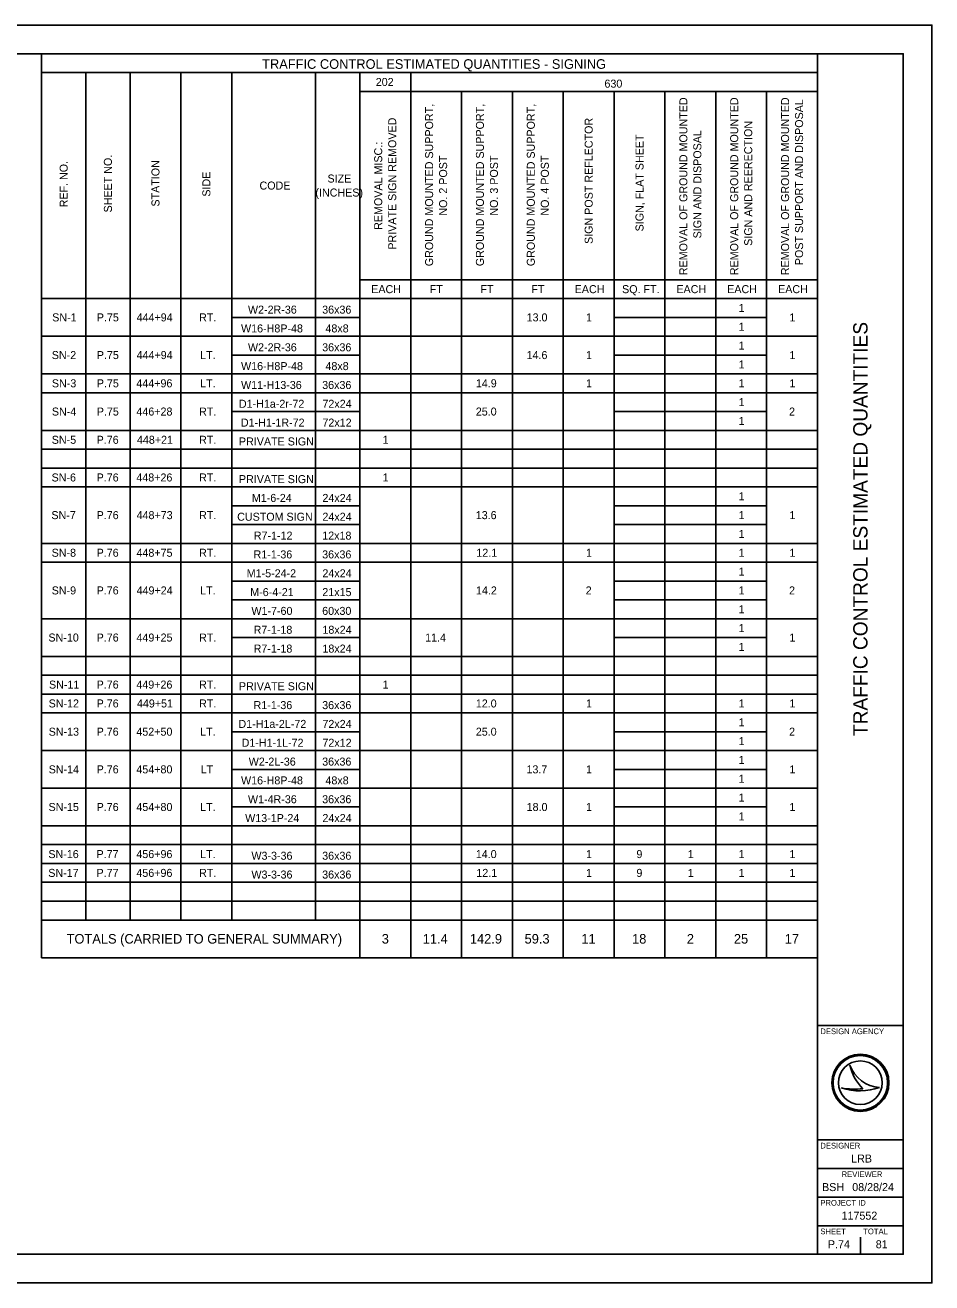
# Model space of a CAD drawing. Extents: x 0 to 34, y 0 to 22.
# Drawn here: x 18.14 to 34, y 0 to 22 of the extents above; entities that cross this region are included whole.
import ezdxf

# ---------------------------------------------------------------- set-up
doc = ezdxf.new("R2010")
doc.units = 0
for name, color, linetype in [('SH_Border', 7, 'Continuous'), ('SH_Cut_Line', 7, 'Continuous'), ('SH_Data', 7, 'Continuous'), ('SH_Text', 7, 'Continuous')]:
    doc.layers.add(name, color=color, linetype=linetype)

msp = doc.modelspace()

# ---------------------------------------------------------------- linework, layer by layer
at = {"layer": 'SH_Border'}
for p, q in [((32, 0.5), (32, 21.5)), ((32, 4.5), (33.5, 4.5)), ((32, 2.5), (33.5, 2.5)), ((32, 2), (33.5, 2)), ((32, 1.5), (33.5, 1.5)), ((32, 1), (33.5, 1))]:
    msp.add_line(p, q, dxfattribs=at)
msp.add_lwpolyline([(1.5, 21.5), (33.5, 21.5), (33.5, 0.5), (1.5, 0.5)], close=True, dxfattribs=at)
at = {"layer": 'SH_Cut_Line'}
msp.add_lwpolyline([(0, 0), (34, 0), (34, 22), (0, 22)], close=True, dxfattribs=at)
at = {"layer": 'SH_Data'}
for p, q in [((32.567, 3.81), (32.567, 3.81)), ((32.417, 3.41), (32.417, 3.41)), ((32.75, 3.5), (32.75, 3.5)), ((33.087, 3.419), (33.087, 3.419)), ((32.375, 0.675), (32.375, 0.675)), ((32.75, 0.5), (32.75, 0.8))]:
    msp.add_line(p, q, dxfattribs=at)
for radius in [0.5, 0.477, 0.477, 0.382]:
    msp.add_circle((32.75, 3.5), radius, dxfattribs=at)
for centre, radius, start, end in [((33.116, 3.998), 0.58, 198.9257, 198.9319), ((33.347, 3.97), 0.796, 191.6379, 191.6421), ((33.116, 3.998), 0.58, 198.9319, 267.1657), ((33.347, 3.97), 0.796, 191.6421, 226.0947), ((32.739, 4.37), 1.013, 251.4576, 290.0832), ((32.648, 4.654), 1.266, 259.4964, 259.4995), ((32.739, 4.37), 1.013, 251.4527, 251.4576), ((32.648, 4.654), 1.266, 259.4995, 276.6672)]:
    msp.add_arc(centre, radius, start, end, dxfattribs=at)
at = {"layer": 'SH_Text'}
for p, q in [((18.428, 21.5), (32, 21.5)), ((18.428, 21.5), (18.428, 5.688)), ((32, 21.5), (32, 5.688)), ((18.428, 21.171), (32, 21.171)), ((19.202, 21.171), (19.202, 6.347)), ((19.976, 21.171), (19.976, 6.347)), ((20.866, 21.171), (20.866, 6.347)), ((21.755, 21.171), (21.755, 6.347)), ((23.221, 21.171), (23.221, 6.347)), ((23.995, 21.171), (23.995, 5.688)), ((24.885, 21.171), (24.885, 5.688)), ((23.995, 20.841), (32, 20.841)), ((25.774, 20.841), (25.774, 5.688)), ((26.664, 20.841), (26.664, 5.688)), ((27.553, 20.841), (27.553, 5.688)), ((28.442, 20.841), (28.442, 5.688)), ((29.332, 20.841), (29.332, 5.688)), ((30.221, 20.841), (30.221, 5.688)), ((31.111, 20.841), (31.111, 6.347)), ((23.995, 17.547), (32, 17.547)), ((18.428, 17.218), (32, 17.218)), ((21.755, 16.888), (23.995, 16.888)), ((28.442, 16.888), (31.111, 16.888)), ((18.428, 16.559), (32, 16.559)), ((21.755, 16.229), (23.995, 16.229)), ((28.442, 16.229), (31.111, 16.229)), ((18.428, 15.9), (32, 15.9)), ((18.428, 15.571), (32, 15.571)), ((21.755, 15.241), (23.995, 15.241)), ((28.442, 15.241), (31.111, 15.241)), ((18.428, 14.912), (32, 14.912)), ((18.428, 14.582), (32, 14.582)), ((18.428, 14.253), (32, 14.253)), ((18.428, 13.924), (32, 13.924)), ((21.755, 13.594), (23.995, 13.594)), ((28.442, 13.594), (31.111, 13.594)), ((21.755, 13.265), (23.995, 13.265)), ((28.442, 13.265), (31.111, 13.265)), ((18.428, 12.935), (32, 12.935)), ((18.428, 12.606), (32, 12.606)), ((21.755, 12.276), (23.995, 12.276)), ((28.442, 12.276), (31.111, 12.276)), ((21.755, 11.947), (23.995, 11.947)), ((28.442, 11.947), (31.111, 11.947)), ((18.428, 11.618), (32, 11.618)), ((21.755, 11.288), (23.995, 11.288)), ((28.442, 11.288), (31.111, 11.288)), ((18.428, 10.959), (32, 10.959)), ((18.428, 10.629), (32, 10.629)), ((18.428, 10.3), (32, 10.3)), ((18.428, 9.971), (32, 9.971)), ((21.755, 9.641), (23.995, 9.641)), ((28.442, 9.641), (31.111, 9.641)), ((18.428, 9.312), (32, 9.312)), ((21.755, 8.982), (23.995, 8.982)), ((28.442, 8.982), (31.111, 8.982)), ((18.428, 8.653), (32, 8.653)), ((21.755, 8.324), (23.995, 8.324)), ((28.442, 8.324), (31.111, 8.324)), ((18.428, 7.994), (32, 7.994)), ((18.428, 7.665), (32, 7.665)), ((18.428, 7.335), (32, 7.335)), ((18.428, 7.006), (32, 7.006)), ((18.428, 6.676), (32, 6.676)), ((18.428, 6.347), (32, 6.347)), ((31.111, 6.347), (31.111, 5.688)), ((18.428, 5.688), (32, 5.688))]:
    msp.add_line(p, q, dxfattribs=at)

# ---------------------------------------------------------------- texts
at = {"layer": 'SH_Data'}
msp.add_text('TRAFFIC CONTROL ESTIMATED QUANTITIES', height=0.25, rotation=90, dxfattribs=at).set_placement((32.875, 9.565))
for s, height, p in [('DESIGN AGENCY', 0.1, (32.05, 4.35)), ('DESIGNER', 0.1, (32.05, 2.35)), ('LRB', 0.14, (32.589, 2.105)), ('REVIEWER', 0.1, (32.422, 1.85)), ('BSH', 0.14, (32.08, 1.605)), ('08/28/24', 0.14, (32.608, 1.605)), ('PROJECT ID', 0.1, (32.05, 1.35)), ('117552', 0.14, (32.421, 1.105)), ('SHEET', 0.1, (32.05, 0.85)), ('TOTAL', 0.1, (32.8, 0.85)), ('P.74', 0.14, (32.182, 0.605)), ('81', 0.14, (33.019, 0.605))]:
    msp.add_text(s, height=height, dxfattribs=at).set_placement(p)
at = {"layer": 'SH_Text'}
for s, height, p in [('TRAFFIC CONTROL ESTIMATED QUANTITIES - SIGNING', 0.168, (22.286, 21.236)), ('202', 0.14, (24.274, 20.936)), ('630', 0.14, (28.274, 20.907)), ('SIZE ', 0.14, (23.43, 19.247)), ('CODE', 0.14, (22.241, 19.124)), ('(INCHES)', 0.14, (23.219, 19.002)), ('EACH', 0.14, (24.195, 17.312)), ('FT', 0.14, (25.217, 17.312)), ('FT', 0.14, (26.106, 17.312)), ('FT', 0.14, (26.995, 17.312)), ('EACH', 0.14, (27.753, 17.312)), ('SQ. FT.', 0.14, (28.582, 17.312)), ('EACH', 0.14, (29.532, 17.312)), ('EACH', 0.14, (30.421, 17.312)), ('EACH', 0.14, (31.311, 17.312)), ('SN-1', 0.14, (18.615, 16.818)), ('P.75', 0.14, (19.395, 16.818)), ('444+94', 0.14, (20.091, 16.818)), ('RT.', 0.14, (21.184, 16.818)), ('W2-2R-36', 0.14, (22.039, 16.954)), ('36x36', 0.14, (23.337, 16.954)), ('13.0', 0.14, (26.913, 16.818)), ('1', 0.14, (27.952, 16.818)), ('1', 0.14, (30.62, 16.983)), ('1', 0.14, (31.509, 16.818)), ('W16-H8P-48', 0.14, (21.918, 16.625)), ('48x8', 0.14, (23.394, 16.625)), ('1', 0.14, (30.62, 16.654)), ('SN-2', 0.14, (18.608, 16.159)), ('P.75', 0.14, (19.395, 16.159)), ('444+94', 0.14, (20.091, 16.159)), ('LT.', 0.14, (21.203, 16.159)), ('W2-2R-36', 0.14, (22.039, 16.295)), ('36x36', 0.14, (23.337, 16.295)), ('14.6', 0.14, (26.912, 16.159)), ('1', 0.14, (27.952, 16.159)), ('1', 0.14, (30.62, 16.324)), ('1', 0.14, (31.509, 16.159)), ('W16-H8P-48', 0.14, (21.918, 15.966)), ('48x8', 0.14, (23.394, 15.966)), ('1', 0.14, (30.62, 15.995)), ('SN-3', 0.14, (18.609, 15.665)), ('P.75', 0.14, (19.395, 15.665)), ('444+96', 0.14, (20.087, 15.665)), ('LT.', 0.14, (21.203, 15.665)), ('W11-H13-36', 0.14, (21.918, 15.636)), ('36x36', 0.14, (23.337, 15.636)), ('14.9', 0.14, (26.025, 15.665)), ('1', 0.14, (27.952, 15.665)), ('1', 0.14, (30.62, 15.665)), ('1', 0.14, (31.509, 15.665)), ('D1-H1a-2r-72', 0.14, (21.88, 15.307)), ('72x24', 0.14, (23.341, 15.307)), ('1', 0.14, (30.62, 15.336)), ('SN-4', 0.14, (18.609, 15.171)), ('P.75', 0.14, (19.395, 15.171)), ('446+28', 0.14, (20.088, 15.171)), ('RT.', 0.14, (21.184, 15.171)), ('25.0', 0.14, (26.024, 15.171)), ('2', 0.14, (31.503, 15.171)), ('D1-H1-1R-72', 0.14, (21.915, 14.978)), ('72x12', 0.14, (23.341, 14.978)), ('1', 0.14, (30.62, 15.006)), ('SN-5', 0.14, (18.607, 14.677)), ('P.76', 0.14, (19.392, 14.677)), ('448+21', 0.14, (20.097, 14.677)), ('RT.', 0.14, (21.184, 14.677)), ('PRIVATE SIGN', 0.14, (21.881, 14.648)), ('1', 0.14, (24.394, 14.677)), ('SN-6', 0.14, (18.604, 14.018)), ('P.76', 0.14, (19.392, 14.018)), ('448+26', 0.14, (20.087, 14.018)), ('RT.', 0.14, (21.184, 14.018)), ('PRIVATE SIGN', 0.14, (21.881, 13.989)), ('1', 0.14, (24.394, 14.018)), ('M1-6-24', 0.14, (22.107, 13.66)), ('24x24', 0.14, (23.341, 13.66)), ('1', 0.14, (30.62, 13.689)), ('SN-7', 0.14, (18.601, 13.359)), ('P.76', 0.14, (19.392, 13.359)), ('448+73', 0.14, (20.091, 13.359)), ('RT.', 0.14, (21.184, 13.359)), ('CUSTOM SIGN', 0.14, (21.85, 13.331)), ('24x24', 0.14, (23.341, 13.331)), ('13.6', 0.14, (26.023, 13.359)), ('1', 0.14, (30.62, 13.359)), ('1', 0.14, (31.509, 13.359)), ('R7-1-12', 0.14, (22.141, 13.001)), ('12x18', 0.14, (23.338, 13.001)), ('1', 0.14, (30.62, 13.03)), ('SN-8', 0.14, (18.605, 12.701)), ('P.76', 0.14, (19.392, 12.701)), ('448+75', 0.14, (20.089, 12.701)), ('RT.', 0.14, (21.184, 12.701)), ('R1-1-36', 0.14, (22.137, 12.672)), ('36x36', 0.14, (23.337, 12.672)), ('12.1', 0.14, (26.033, 12.701)), ('1', 0.14, (27.952, 12.701)), ('1', 0.14, (30.62, 12.701)), ('1', 0.14, (31.509, 12.701)), ('M1-5-24-2', 0.14, (22.017, 12.342)), ('24x24', 0.14, (23.341, 12.342)), ('1', 0.14, (30.62, 12.371)), ('SN-9', 0.14, (18.606, 12.042)), ('P.76', 0.14, (19.392, 12.042)), ('449+24', 0.14, (20.091, 12.042)), ('LT.', 0.14, (21.203, 12.042)), ('M-6-4-21', 0.14, (22.079, 12.013)), ('21x15', 0.14, (23.339, 12.013)), ('14.2', 0.14, (26.027, 12.042)), ('2', 0.14, (27.945, 12.042)), ('1', 0.14, (30.62, 12.042)), ('2', 0.14, (31.503, 12.042)), ('W1-7-60', 0.14, (22.099, 11.684)), ('60x30', 0.14, (23.337, 11.684)), ('1', 0.14, (30.62, 11.712)), ('R7-1-18', 0.14, (22.138, 11.354)), ('18x24', 0.14, (23.341, 11.354)), ('1', 0.14, (30.62, 11.383)), ('SN-10', 0.14, (18.549, 11.218)), ('P.76', 0.14, (19.392, 11.218)), ('449+25', 0.14, (20.089, 11.218)), ('RT.', 0.14, (21.184, 11.218)), ('11.4', 0.14, (25.138, 11.218)), ('1', 0.14, (31.509, 11.218)), ('R7-1-18', 0.14, (22.138, 11.025)), ('18x24', 0.14, (23.341, 11.025)), ('1', 0.14, (30.62, 11.054)), ('SN-11', 0.14, (18.559, 10.395)), ('P.76', 0.14, (19.392, 10.395)), ('449+26', 0.14, (20.087, 10.395)), ('RT.', 0.14, (21.184, 10.395)), ('PRIVATE SIGN', 0.14, (21.881, 10.366)), ('1', 0.14, (24.394, 10.395)), ('SN-12', 0.14, (18.552, 10.065)), ('P.76', 0.14, (19.392, 10.065)), ('449+51', 0.14, (20.097, 10.065)), ('RT.', 0.14, (21.184, 10.065)), ('R1-1-36', 0.14, (22.137, 10.036)), ('36x36', 0.14, (23.337, 10.036)), ('12.0', 0.14, (26.024, 10.065)), ('1', 0.14, (27.952, 10.065)), ('1', 0.14, (30.62, 10.065)), ('1', 0.14, (31.509, 10.065)), ('SN-13', 0.14, (18.553, 9.571)), ('P.76', 0.14, (19.392, 9.571)), ('452+50', 0.14, (20.087, 9.571)), ('LT.', 0.14, (21.203, 9.571)), ('D1-H1a-2L-72', 0.14, (21.872, 9.707)), ('72x24', 0.14, (23.341, 9.707)), ('25.0', 0.14, (26.024, 9.571)), ('1', 0.14, (30.62, 9.736)), ('2', 0.14, (31.503, 9.571)), ('D1-H1-1L-72', 0.14, (21.928, 9.378)), ('72x12', 0.14, (23.341, 9.378)), ('1', 0.14, (30.62, 9.406)), ('SN-14', 0.14, (18.553, 8.912)), ('P.76', 0.14, (19.392, 8.912)), ('454+80', 0.14, (20.087, 8.912)), ('LT', 0.14, (21.211, 8.912)), ('W2-2L-36', 0.14, (22.052, 9.048)), ('36x36', 0.14, (23.337, 9.048)), ('13.7', 0.14, (26.91, 8.912)), ('1', 0.14, (27.952, 8.912)), ('1', 0.14, (30.62, 9.077)), ('1', 0.14, (31.509, 8.912)), ('W16-H8P-48', 0.14, (21.918, 8.719)), ('48x8', 0.14, (23.394, 8.719)), ('1', 0.14, (30.62, 8.748)), ('SN-15', 0.14, (18.551, 8.254)), ('P.76', 0.14, (19.392, 8.254)), ('454+80', 0.14, (20.087, 8.254)), ('LT.', 0.14, (21.203, 8.254)), ('W1-4R-36', 0.14, (22.039, 8.389)), ('36x36', 0.14, (23.337, 8.389)), ('18.0', 0.14, (26.913, 8.254)), ('1', 0.14, (27.952, 8.254)), ('1', 0.14, (30.62, 8.418)), ('1', 0.14, (31.509, 8.254)), ('W13-1P-24', 0.14, (21.99, 8.06)), ('24x24', 0.14, (23.341, 8.06)), ('1', 0.14, (30.62, 8.089)), ('SN-16', 0.14, (18.548, 7.43)), ('P.77', 0.14, (19.39, 7.43)), ('456+96', 0.14, (20.087, 7.43)), ('LT.', 0.14, (21.203, 7.43)), ('W3-3-36', 0.14, (22.099, 7.401)), ('36x36', 0.14, (23.337, 7.401)), ('14.0', 0.14, (26.024, 7.43)), ('1', 0.14, (27.952, 7.43)), ('9', 0.14, (28.833, 7.43)), ('1', 0.14, (29.731, 7.43)), ('1', 0.14, (30.62, 7.43)), ('1', 0.14, (31.509, 7.43)), ('SN-17', 0.14, (18.546, 7.101)), ('P.77', 0.14, (19.39, 7.101)), ('456+96', 0.14, (20.087, 7.101)), ('RT.', 0.14, (21.184, 7.101)), ('W3-3-36', 0.14, (22.099, 7.072)), ('36x36', 0.14, (23.337, 7.072)), ('12.1', 0.14, (26.033, 7.101)), ('1', 0.14, (27.952, 7.101)), ('9', 0.14, (28.833, 7.101)), ('1', 0.14, (29.731, 7.101)), ('1', 0.14, (30.62, 7.101)), ('1', 0.14, (31.509, 7.101)), ('TOTALS (CARRIED TO GENERAL SUMMARY)', 0.168, (18.867, 5.934)), ('3', 0.168, (24.379, 5.934)), ('11.4', 0.168, (25.096, 5.934)), ('142.9', 0.168, (25.92, 5.934)), ('59.3', 0.168, (26.877, 5.934)), ('11', 0.168, (27.87, 5.934)), ('18', 0.168, (28.757, 5.934)), ('2', 0.168, (29.715, 5.934)), ('25', 0.168, (30.538, 5.934)), ('17', 0.168, (31.427, 5.934))]:
    msp.add_text(s, height=height, dxfattribs=at).set_placement(p)
for s, p in [('REMOVAL OF GROUND MOUNTED ', (29.724, 17.627)), ('REMOVAL OF GROUND MOUNTED ', (30.613, 17.627)), ('REMOVAL OF GROUND MOUNTED ', (31.503, 17.627)), ('POST SUPPORT AND DISPOSAL', (31.748, 17.802)), ('GROUND MOUNTED SUPPORT,', (25.277, 17.784)), ('GROUND MOUNTED SUPPORT,', (26.166, 17.784)), ('GROUND MOUNTED SUPPORT,', (27.056, 17.784)), ('PRIVATE SIGN REMOVED', (24.632, 18.073)), ('SIGN POST REFLECTOR', (28.068, 18.173)), ('SIGN AND REERECTION', (30.858, 18.14)), ('SIGN, FLAT SHEET', (28.957, 18.392)), ('SIGN AND DISPOSAL', (29.969, 18.27)), ('REMOVAL MISC.:', (24.387, 18.42)), ('REF. NO.', (18.885, 18.813)), ('SHEET NO.', (19.659, 18.724)), ('STATION', (20.491, 18.827)), ('NO. 2 POST', (25.522, 18.668)), ('NO. 3 POST', (26.411, 18.668)), ('NO. 4 POST', (27.301, 18.668)), ('SIDE', (21.381, 19))]:
    msp.add_text(s, height=0.14, rotation=90, dxfattribs=at).set_placement(p)

doc.saveas('drawing.dxf')
